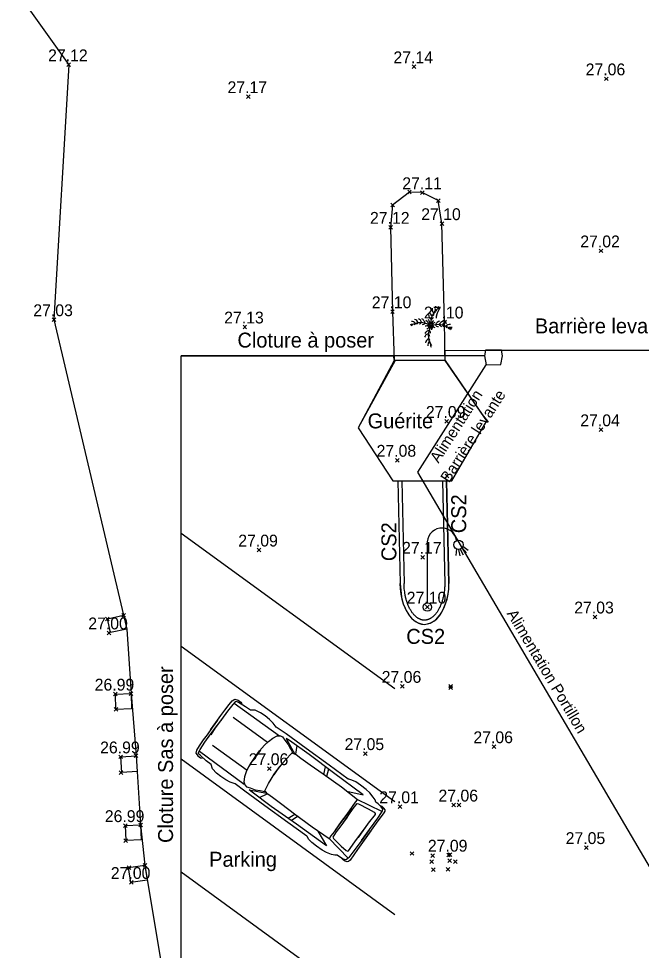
# Model space of a CAD drawing. Extents: x 37864 to 38032, y 453991 to 454052.
# Drawn here: x 37879.07 to 37894.08, y 454016.08 to 454038.52 of the extents above; entities that cross this region are included whole.
import ezdxf

# ---------------------------------------------------------------- set-up
doc = ezdxf.new("R2010")
doc.units = 0
for name, color, linetype in [('DH_CALCUL SURFACE-TEXTE', 7, 'Continuous'), ('GO_POTEAU', 7, 'Continuous'), ('PS_Bolt', 7, 'Continuous'), ('PS_Const', 7, 'Continuous'), ('PS_Dim', 7, 'Continuous'), ('PS_Hidden', 7, 'Continuous'), ('PS_Object', 7, 'Continuous'), ('PS_Plate', 7, 'Continuous'), ('PS_RoofWall', 7, 'Continuous'), ('PS_Shape', 7, 'Continuous'), ('PS_Solid', 7, 'Continuous'), ('PS_Weld', 7, 'Continuous'), ('SO_SANITAIRE DETAILLE', 7, 'Continuous')]:
    doc.layers.add(name, color=color, linetype=linetype)

# ---------------------------------------------------------------- blocks, each defined once
blk = doc.blocks.new('V-EP-CANDELAB')
for p, q in [((0, 0.1), (0, 1.5)), ((0.700628, 1.399688), (0.684459, 1.240974)), ((0.752708, 1.388229), (0.78082, 1.234594)), ((0.792944, 1.396773), (0.86024, 1.256612)), ((0.830421, 1.422331), (0.931041, 1.303495)), ((0.855244, 1.462269), (0.984837, 1.372556))]:
    blk.add_line(p, q)
for centre, radius in [((0.75, 1.5), 0.111803), ((0, 0), 0.1)]:
    blk.add_circle(centre, radius)
blk.add_arc((0.35, 1.55), 0.353553, 8.130102, 188.130102)
blk = doc.blocks.new('COCO')
blk.add_line((0.057, -0.022), (0.067, -0.026))
for points in [[(-0.124, 0.143), (-0.094, 0.115), (-0.067, 0.064), (-0.056, 0.038)], [(-0.056, 0.129), (-0.041, 0.09), (-0.035, 0.067)], [(-0.001, 0.067), (0.025, 0.08), (0.054, 0.117)], [(0.089, 0.085), (0.062, 0.069), (0.044, 0.054)], [(-0.088, -0.065), (-0.061, -0.045), (-0.025, -0.027)], [(0.018, -0.083), (0.009, -0.054), (-0.007, -0.023)]]:
    blk.add_lwpolyline(points)
for centre, radius, start, end in [((0.217, 0.419), 0.124, 153.486, 204.7238), ((0.228, 0.411), 0.0708, 123.5073, 175.8595), ((0.108, 0.288), 0.171, 185.1978, 230.7826), ((0.107, 0.35), 0.137, 181.3654, 233.0958), ((0.422, 0.078), 0.429, 127.5514, 182.6102), ((0.135, 0.395), 0.11, 162.3561, 228.705), ((0.008, 0.312), 0.0735, 282.9298, 332.2559), ((0.064, 0.356), 0.0442, 267.7529, 335.4438), ((0.113, 0.399), 0.033, 254.2928, 325.2228), ((0.16, 0.458), 0.0398, 270.4795, 326.1231), ((-0.469, -0.031), 0.0708, 68.8618, 121.214), ((-0.482, 0.051), 0.0398, 278.5982, 334.2418), ((-0.471, -0.017), 0.124, 39.9975, 91.2353), ((-0.251, -0.348), 0.429, 62.3639, 117.1699), ((-0.409, 0.068), 0.033, 279.4985, 350.4285), ((-0.415, 0.047), 0.11, 16.0163, 82.3652), ((-0.35, 0.094), 0.0442, 269.2775, 336.9684), ((-0.363, 0.053), 0.137, 11.6255, 63.3559), ((-0.286, 0.126), 0.0735, 272.4654, 321.7915), ((-0.307, 0.025), 0.171, 13.9387, 59.5235), ((-0.198, 0.112), 0.0737, 255.9805, 321.5114), ((-0.137, 0.118), 0.117, 265.9712, 314.0621), ((-0.069, 0.004), 0.00838, 155.1287, 247.6813), ((-0.035, -0.01), 0.0451, 111.1263, 157.9145), ((-0.067, 0.038), 0.0424, 263.0421, 312.9115), ((0.108, 0.203), 0.18, 192.4617, 204.4421), ((-0.006, -0.039), 0.0564, 111.1263, 157.9145), ((-0.23, -0.011), 0.18, 14.3805, 16.2304), ((-0.044, 0.06), 0.0105, 68.2237, 160.7763), ((-0.001, 0.06), 0.053, 176.1371, 214.6761), ((-0.054, 0.015), 0.0178, 333.913, 79.7857), ((-0.059, 0.017), 0.0564, 33.1475, 71.0095), ((-0.251, -0.348), 0.429, 54.2202, 60.5021), ((-0.029, 0.043), 0.0223, 247.0081, 352.8808), ((-0.03, -0.008), 0.0223, 333.913, 79.7857), ((-0.224, -0.046), 0.214, 15.7859, 18.5602), ((0.137, 0.183), 0.214, 225.9092, 228.9354), ((-0.059, 0.017), 0.0564, 24.2214, 26.0625), ((-0.048, 0.174), 0.117, 290.6592, 293.8486), ((0.015, -0.022), 0.0223, 56.5554, 162.4281), ((0.422, 0.078), 0.429, 185.1526, 190.5011), ((-0.066, 0.138), 0.132, 298.2511, 300.0757), ((0.045, 0.01), 0.053, 147.9454, 150.6531), ((0.02, 0.033), 0.0223, 171.6547, 277.5273), ((-0.017, 0.228), 0.0737, 283.2099, 348.7407), ((0.17, -0.394), 0.429, 50.4397, 113.3894), ((0.045, 0.01), 0.053, 100.7837, 124.5304), ((0.036, -0.006), 0.0178, 87.891, 158.5901), ((0.209, -0.093), 0.214, 151.1123, 151.8237), ((-0.012, 0.054), 0.0564, 308.868, 355.6561), ((0.034, 0.051), 0.0105, 352.8703, 85.4229), ((0.02, -0.028), 0.0424, 17.0201, 66.8895), ((-0.048, 0.174), 0.117, 331.1939, 338.75), ((0.209, -0.093), 0.214, 122.7468, 123.9873), ((0.279, -0.058), 0.192, 112.2412, 152.661), ((0.164, 0.046), 0.058, 195.1268, 282.5722), ((0.322, -0.023), 0.14, 101.8722, 155.687), ((0.302, 0.119), 0.137, 217.8706, 249.7656), ((0.378, -0.017), 0.109, 94.1148, 159.0322), ((0.337, 0.044), 0.0641, 200.3063, 250.058), ((0.447, -0.087), 0.123, 79.7314, 138.9221), ((-0.028, -0.321), 0.14, 105.2055, 159.0203), ((0.013, -0.284), 0.192, 108.2316, 148.6514), ((0.059, -0.221), 0.214, 133.3675, 138.1457), ((0.362, -0.23), 0.429, 147.5032, 210.4529), ((-0.165, -0.279), 0.137, 11.127, 43.022), ((-0.049, -0.022), 0.0105, 155.1287, 247.6813), ((-0.046, 0.021), 0.053, 263.0421, 312.9115), ((-0.071, -0.155), 0.058, 338.3203, 65.7657), ((-0.113, -0.103), 0.132, 37.1668, 39.7532), ((0.048, -0.002), 0.0564, 193.7688, 240.5569), ((-0.113, -0.103), 0.132, 3.3838, 8.5978), ((0.026, -0.042), 0.0105, 237.7711, 330.3237), ((-0.016, -0.034), 0.053, 345.6845, 35.5539), ((0.051, 0.021), 0.0451, 249.948, 271.8925), ((0.052, -0.015), 0.00838, 269.1067, 1.6593), ((0.119, 0.095), 0.132, 246.6411, 257.5088), ((0.391, -0.003), 0.0365, 184.8659, 248.5993), ((0.438, -0.048), 0.0241, 163.1519, 234.069), ((0.472, -0.243), 0.21, 80.7993, 105.8694), ((0.452, -0.131), 0.0708, 46.3956, 98.7477), ((0.482, -0.054), 0.0398, 193.3678, 249.0114), ((-0.023, -0.417), 0.11, 109.2993, 175.6482), ((0.044, -0.469), 0.124, 133.2805, 184.5183), ((-0.074, -0.354), 0.0442, 2.5605, 70.2514), ((-0.044, -0.412), 0.033, 12.7815, 83.7115), ((0.058, -0.467), 0.0708, 162.1448, 214.497), ((-0.023, -0.485), 0.0398, 11.8811, 67.5248)]:
    blk.add_arc(centre, radius, start, end)
blk = doc.blocks.new('POTO_REC')
at = {"layer": 'PS_Weld'}
for p, q in [((0, 1), (1, 1)), ((0, 0), (0, 1)), ((1, 1), (1, 0)), ((1, 0), (0, 0))]:
    blk.add_line(p, q, dxfattribs=at)
blk = doc.blocks.new('POINT_DISPLAY')
for p, q in [((-0.04375, -0.04375), (0.04375, 0.04375)), ((-0.04375, 0.04375), (0.04375, -0.04375))]:
    blk.add_line(p, q)
blk = doc.blocks.new('POINTCOT')
blk.add_blockref('POINT_DISPLAY', (0, 0))
blk = doc.blocks.new('2AUTOT')
at = {"layer": 'PS_Object'}
for points in [[(-2.2368, -0.1259), (-2.2386, 0.2015), (-2.2354, 0.5377), (-2.2324, 0.697), (-2.2268, 0.7426), (-2.2084, 0.7838), (-2.144, 0.8083), (-2.0432, 0.8164), (-1.9712, 0.8202), (-1.9275, 0.8508), (-1.8518, 0.8827), (-1.7249, 0.9185), (-1.608, 0.9323), (-1.4401, 0.9339), (-1.298, 0.9313), (-1.1945, 0.9113), (-1.1215, 0.8812), (-1.1104, 0.8767), (-0.5447, 0.878), (0.1409, 0.8813), (0.7386, 0.8794), (1.0309, 0.8727), (1.1466, 0.9086), (1.2652, 0.9239), (1.4092, 0.9345), (1.5433, 0.9275), (1.677, 0.9028), (1.7685, 0.8402), (1.9202, 0.833), (2.1132, 0.8123), (2.1691, 0.8089), (2.1877, 0.7793), (2.1974, 0.6996), (2.2046, 0.4901), (2.2064, 0.2453), (2.2048, -0.0084), (2.1947, -0.2029)], [(-2.2848, -0.1314), (-2.2888, 0.4217), (-2.2909, 0.7314), (-2.2836, 0.7814), (-2.2655, 0.8064), (-2.2141, 0.8192), (-2.1613, 0.8262), (-2.1183, 0.817), (-2.0976, 0.8109)], [(-2.2271, 0.7235), (-1.5742, 0.6061)], [(-1.2494, 0.6227), (-1.6267, 0.7865), (-0.7381, 0.7926), (0.002, 0.8043), (0.5788, 0.7967), (0.6713, 0.7886), (0.2844, 0.6088)], [(-0.65, 0.6296), (-0.5861, 0.8002)], [(-0.5719, 0.6231), (-0.4967, 0.7965)], [(0.2639, 0.6208), (0.3616, 0.8058)], [(1.007, -0.1403), (1.0182, 0.0307), (1.0193, 0.1767), (1.0035, 0.3523), (0.9788, 0.4823), (0.9395, 0.605), (0.8856, 0.7131), (0.8242, 0.7593), (0.7669, 0.7701), (0.68, 0.7398), (0.5514, 0.701), (0.445, 0.6503), (0.3774, 0.6228), (0.3483, 0.6068), (0.3601, 0.5536), (0.3827, 0.3957), (0.3915, 0.2688), (0.4032, 0.1301), (0.4012, 0.0239), (0.4006, -0.0941)], [(2.1886, 0.7409), (0.8432, 0.7503)], [(2.2747, -0.1136), (2.2724, 0.1046), (2.27, 0.3126), (2.2713, 0.4704), (2.2666, 0.6444), (2.2593, 0.761), (2.2286, 0.8291), (2.1508, 0.8577), (2.0757, 0.8569), (2.0322, 0.8366)], [(-1.6299, -0.0629), (-1.6283, 0.1907), (-1.6233, 0.3735), (-1.6284, 0.5254), (-1.6632, 0.5449), (-1.9214, 0.5809), (-2.084, 0.5999), (-2.1242, 0.5899), (-2.1341, 0.5723), (-2.1215, 0.3067), (-2.1311, -0.1149)], [(-1.5848, -0.2978), (-1.5832, -0.0427), (-1.5806, 0.1815), (-1.5811, 0.4086), (-1.5755, 0.5339), (-1.5821, 0.6091), (-1.0895, 0.6288), (-0.5543, 0.6215), (-0.1709, 0.614), (0.1055, 0.6117), (0.2493, 0.6106), (0.3289, 0.5937), (0.3607, 0.5846)], [(-2.2368, 0.1834), (-2.2386, -0.144), (-2.2354, -0.4802), (-2.2324, -0.6394), (-2.2268, -0.6851), (-2.2084, -0.7263), (-2.144, -0.7508), (-2.0432, -0.7588), (-1.9712, -0.7627), (-1.9275, -0.7933), (-1.8518, -0.8251), (-1.7249, -0.861), (-1.608, -0.8748), (-1.4401, -0.8764), (-1.298, -0.8738), (-1.1945, -0.8538), (-1.1215, -0.8237), (-1.1104, -0.8192), (-0.5447, -0.8205), (0.1409, -0.8238), (0.7386, -0.8219), (1.0309, -0.8151), (1.1466, -0.8511), (1.2652, -0.8663), (1.4092, -0.877), (1.5433, -0.87), (1.677, -0.8453), (1.7685, -0.7827), (1.9202, -0.7755), (2.1132, -0.7548), (2.1691, -0.7514), (2.1877, -0.7218), (2.1974, -0.642), (2.2046, -0.4326), (2.2064, -0.1878), (2.2048, 0.0659), (2.1947, 0.2605)], [(-1.5848, 0.3553), (-1.5832, 0.1002), (-1.5806, -0.1239), (-1.5811, -0.351), (-1.5755, -0.4764), (-1.5821, -0.5516), (-1.0895, -0.5712), (-0.5543, -0.564), (-0.1709, -0.5565), (0.1055, -0.5542), (0.2493, -0.5531), (0.3289, -0.5362), (0.3607, -0.5271)], [(0.9812, 0.4439), (2.0072, 0.4474)], [(-2.2848, 0.1889), (-2.2888, -0.3641), (-2.2909, -0.6738), (-2.2836, -0.7239), (-2.2655, -0.7488), (-2.2141, -0.7617), (-2.1613, -0.7686), (-2.1183, -0.7595), (-2.0976, -0.7534)], [(-1.6299, 0.1205), (-1.6283, -0.1332), (-1.6233, -0.316), (-1.6284, -0.4679), (-1.6632, -0.4874), (-1.9214, -0.5234), (-2.084, -0.5424), (-2.1242, -0.5324), (-2.1341, -0.5148), (-2.1215, -0.2492), (-2.1311, 0.1725)], [(1.007, 0.1978), (1.0182, 0.0268), (1.0193, -0.1192), (1.0035, -0.2948), (0.9788, -0.4248), (0.9395, -0.5475), (0.8856, -0.6556), (0.8242, -0.7018), (0.7669, -0.7126), (0.68, -0.6823), (0.5514, -0.6435), (0.445, -0.5928), (0.3774, -0.5653), (0.3483, -0.5493), (0.3601, -0.4961), (0.3827, -0.3382), (0.3915, -0.2113), (0.4032, -0.0725), (0.4012, 0.0336), (0.4006, 0.1516)], [(2.2747, 0.1711), (2.2724, -0.0471), (2.27, -0.2551), (2.2713, -0.4129), (2.2666, -0.5869), (2.2593, -0.7035), (2.2286, -0.7716), (2.1508, -0.8002), (2.0757, -0.7993), (2.0322, -0.779)], [(0.9812, -0.3864), (2.0072, -0.3899)], [(-2.2271, -0.666), (-1.5742, -0.5486)], [(-1.2494, -0.5652), (-1.6267, -0.7289), (-0.7381, -0.735), (0.002, -0.7468), (0.5788, -0.7392), (0.6713, -0.731), (0.2844, -0.5513)], [(-0.65, -0.5721), (-0.5861, -0.7427)], [(-0.5719, -0.5656), (-0.4967, -0.739)], [(0.2639, -0.5633), (0.3616, -0.7483)], [(2.1886, -0.6834), (0.8432, -0.6928)]]:
    blk.add_lwpolyline(points, dxfattribs=at)
blk = doc.blocks.new('AUTD')
at = {"layer": 'PS_Object'}
blk.add_blockref('2AUTOT', (-2.1886, 0.6834), dxfattribs=at)

msp = doc.modelspace()

# ---------------------------------------------------------------- linework, layer by layer
at = {"layer": 'PS_Dim'}
for p, q in [((37882.985, 454004.477), (37882.985, 454030.398)), ((37890.298, 454030.398), (37882.985, 454030.398)), ((37890.702, 454030.534), (37896.649, 454030.534))]:
    msp.add_line(p, q, dxfattribs=at)
at = {"layer": 'PS_Hidden'}
for p, q in [((37888.135, 454022.381), (37882.985, 454026.123)), ((37888.135, 454019.662), (37882.985, 454023.403)), ((37888.135, 454016.942), (37882.985, 454020.684)), ((37888.135, 454014.223), (37882.985, 454017.965))]:
    msp.add_line(p, q, dxfattribs=at)
at = {"layer": 'PS_Object'}
for p, q in [((37888.689, 454027.599), (37890.334, 454030.185)), ((37895.353, 454016.257), (37888.689, 454027.599))]:
    msp.add_line(p, q, dxfattribs=at)
msp.add_lwpolyline([(37882.985, 454004.477), (37882.985, 454030.398), (37888.093, 454030.398), (37888.117, 454030.285), (37887.249, 454028.666), (37888.087, 454027.388), (37888.205, 454027.388), (37888.26, 454024.917), (37888.293, 454024.591), (37888.339, 454024.424), (37888.407, 454024.265), (37888.488, 454024.141), (37888.536, 454024.084), (37888.591, 454024.033), (37888.65, 454023.991), (37888.708, 454023.962), (37888.779, 454023.94), (37888.849, 454023.934), (37888.985, 454023.959), (37889.121, 454024.044), (37889.24, 454024.186), (37889.319, 454024.328), (37889.374, 454024.475), (37889.41, 454024.622), (37889.433, 454024.777), (37889.438, 454024.917), (37889.382, 454027.388), (37889.512, 454027.388), (37890.353, 454028.831), (37889.352, 454030.285), (37889.343, 454030.528), (37899.117, 454030.549)], dxfattribs=at)
at = {"layer": 'PS_Plate'}
msp.add_lwpolyline([(37890.323, 454030.534), (37890.298, 454030.398), (37890.334, 454030.185), (37890.688, 454030.19), (37890.729, 454030.398), (37890.702, 454030.534), (37890.323, 454030.534)], dxfattribs=at)
at = {"layer": 'PS_Shape'}
msp.add_line((37889.382, 454027.388), (37889.438, 454024.917), dxfattribs=at)
at = {"layer": 'PS_Solid'}
msp.add_lwpolyline([(37888.144, 454030.285), (37887.249, 454028.666), (37888.087, 454027.388), (37889.512, 454027.388), (37890.353, 454028.831), (37889.354, 454030.285), (37888.144, 454030.285)], dxfattribs=at)
at = {"layer": 'SO_SANITAIRE DETAILLE'}
for p, q in [((37882.985, 454004.477), (37882.985, 454030.285)), ((37888.205, 454027.388), (37888.261, 454024.917)), ((37888.305, 454027.39), (37888.361, 454024.919)), ((37889.282, 454027.385), (37889.338, 454024.914)), ((37889.382, 454027.388), (37889.438, 454024.917))]:
    msp.add_line(p, q, dxfattribs=at)
for points in [[(37877.767, 454040.919), (37880.278, 454037.408), (37879.922, 454031.271), (37881.601, 454024.153), (37881.601, 454024.153), (37881.601, 454024.153), (37881.675, 454023.821), (37881.781, 454022.267), (37881.901, 454020.769), (37881.927, 454020.39), (37882.008, 454019.105), (37882.114, 454018.134), (37882.561, 454015.43), (37882.656, 454013.593), (37882.577, 454012.12), (37882.592, 454010.925), (37882.785, 454009.367), (37882.96, 454007.587), (37882.985, 454004.477)], [(37889.352, 454030.285), (37889.334, 454031.215), (37889.269, 454033.583), (37889.181, 454034.136), (37888.798, 454034.328), (37888.489, 454034.343), (37888.081, 454034.029), (37888.035, 454033.494), (37888.079, 454031.462), (37888.117, 454030.285)]]:
    msp.add_lwpolyline(points, dxfattribs=at)
msp.add_ellipse((37888.849, 454024.917), major_axis=(0, 0.983), ratio=0.599267, start_param=1.570796, end_param=4.712389, dxfattribs=at)
msp.add_open_spline([(37889.338, 454024.917), (37889.338, 454024.855), (37889.334, 454024.795), (37889.323, 454024.706), (37889.319, 454024.677), (37889.309, 454024.62), (37889.303, 454024.592), (37889.289, 454024.537), (37889.281, 454024.51), (37889.265, 454024.458), (37889.256, 454024.433), (37889.236, 454024.384), (37889.226, 454024.36), (37889.203, 454024.315), (37889.192, 454024.294), (37889.167, 454024.252), (37889.154, 454024.233), (37889.128, 454024.197), (37889.115, 454024.181), (37889.087, 454024.151), (37889.074, 454024.137), (37889.046, 454024.112), (37889.031, 454024.101), (37889.003, 454024.081), (37888.989, 454024.073), (37888.968, 454024.062), (37888.961, 454024.059), (37888.947, 454024.053), (37888.94, 454024.05), (37888.926, 454024.045), (37888.919, 454024.043), (37888.905, 454024.04), (37888.898, 454024.038), (37888.884, 454024.036), (37888.877, 454024.035), (37888.863, 454024.034), (37888.856, 454024.034), (37888.842, 454024.034), (37888.835, 454024.034), (37888.821, 454024.035), (37888.814, 454024.036), (37888.8, 454024.038), (37888.793, 454024.04), (37888.779, 454024.043), (37888.772, 454024.045), (37888.758, 454024.05), (37888.751, 454024.053), (37888.737, 454024.059), (37888.73, 454024.062), (37888.709, 454024.073), (37888.694, 454024.081), (37888.666, 454024.101), (37888.652, 454024.112), (37888.624, 454024.137), (37888.61, 454024.151), (37888.583, 454024.181), (37888.569, 454024.197), (37888.543, 454024.233), (37888.53, 454024.252), (37888.506, 454024.294), (37888.494, 454024.315), (37888.472, 454024.36), (37888.461, 454024.384), (37888.442, 454024.433), (37888.433, 454024.458), (37888.416, 454024.51), (37888.408, 454024.537), (37888.395, 454024.592), (37888.389, 454024.62), (37888.378, 454024.677), (37888.374, 454024.706), (37888.363, 454024.795), (37888.36, 454024.855), (37888.36, 454024.917)], degree=3, dxfattribs=at)

# ---------------------------------------------------------------- block references
at = {"layer": 'DH_CALCUL SURFACE-TEXTE', "rotation": 2.2526485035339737e-05}
for p in [(37880.278, 454037.408), (37888.599, 454037.359), (37893.232, 454037.069), (37884.602, 454036.64), (37888.489, 454034.343), (37888.798, 454034.328), (37889.181, 454034.136), (37888.081, 454034.029), (37888.035, 454033.494), (37889.269, 454033.583), (37893.102, 454032.927), (37888.079, 454031.462), (37879.922, 454031.271), (37889.334, 454031.215), (37884.521, 454031.094), (37889.008, 454031.118), (37889.381, 454028.822), (37893.102, 454028.62), (37888.194, 454027.886), (37889.394, 454027.509), (37884.861, 454025.724), (37888.808, 454025.55), (37888.92, 454024.35), (37881.208, 454024.066), (37881.601, 454024.153), (37892.956, 454024.112), (37881.246, 454023.729), (37888.317, 454022.442), (37889.481, 454022.445), (37881.401, 454022.255), (37881.781, 454022.267), (37889.48, 454022.41), (37881.415, 454021.889), (37890.526, 454020.988), (37881.532, 454020.744), (37881.901, 454020.769), (37887.422, 454020.823), (37885.113, 454020.46), (37881.54, 454020.365), (37888.26, 454019.545), (37889.553, 454019.581), (37889.685, 454019.585), (37881.645, 454019.089), (37882.008, 454019.105), (37881.646, 454018.724), (37888.55, 454018.416), (37889.465, 454018.387), (37892.75, 454018.56), (37889.026, 454018.217), (37889.05, 454018.363), (37889.429, 454018.377), (37889.456, 454018.241), (37889.591, 454018.219), (37881.729, 454018.077), (37882.114, 454018.134), (37889.061, 454018.028), (37889.415, 454018.032), (37881.789, 454017.721)]:
    msp.add_blockref('POINTCOT', p, dxfattribs=at)
at = {"layer": 'PS_Bolt'}
for p, xscale, yscale, rotation in [((37881.601, 454024.153), 0.4, 0.3400000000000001, -167.44146717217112), ((37881.781, 454022.267), 0.3800000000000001, 0.37, -178.2062050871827), ((37881.901, 454020.769), 0.37000000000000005, 0.38, -176.09201026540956), ((37882.008, 454019.105), 0.3599999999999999, 0.35999999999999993, -177.5289290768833), ((37882.114, 454018.134), 0.4000000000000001, 0.3599999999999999, -171.57385078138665)]:
    msp.add_blockref('POTO_REC', p, dxfattribs=dict(at, xscale=xscale, yscale=yscale, rotation=rotation))
at = {"layer": 'PS_Const', "rotation": 2.2526485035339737e-05}
msp.add_blockref('COCO', (37889.008, 454031.118), dxfattribs=at)
at = {"layer": 'PS_Hidden', "rotation": 143.99999999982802}
msp.add_blockref('AUTD', (37884.263, 454022.035), dxfattribs=at)
at = {"layer": 'PS_RoofWall', "rotation": 2.2526485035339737e-05}
msp.add_blockref('V-EP-CANDELAB', (37888.92, 454024.35), dxfattribs=at)

# ---------------------------------------------------------------- texts
at = {"layer": 'GO_POTEAU'}
for s, p in [('27.12', (37879.78, 454037.492)), ('27.14', (37888.101, 454037.443)), ('27.06', (37892.734, 454037.153)), ('27.17', (37884.104, 454036.724)), ('27.11', (37888.315, 454034.412)), ('27.10', (37888.771, 454033.667)), ('27.12', (37887.537, 454033.578)), ('27.02', (37892.604, 454033.011)), ('27.10', (37887.581, 454031.546)), ('27.03', (37879.424, 454031.354)), ('27.13', (37884.023, 454031.178)), ('27.10', (37888.836, 454031.299)), ('27.09', (37888.883, 454028.906)), ('27.04', (37892.604, 454028.704)), ('27.08', (37887.696, 454027.97)), ('27.09', (37884.363, 454025.808)), ('27.17', (37888.31, 454025.634)), ('27.10', (37888.422, 454024.433)), ('27.03', (37892.458, 454024.196)), ('27.00', (37880.748, 454023.813)), ('27.06', (37887.819, 454022.526)), ('26.99', (37880.903, 454022.339)), ('27.06', (37890.028, 454021.072)), ('27.05', (37886.924, 454020.907)), ('26.99', (37881.034, 454020.827)), ('27.06', (37884.615, 454020.544)), ('27.01', (37887.762, 454019.628)), ('27.06', (37889.187, 454019.668)), ('26.99', (37881.147, 454019.173)), ('27.05', (37892.252, 454018.644)), ('27.09', (37888.931, 454018.461)), ('27.00', (37881.292, 454017.804))]:
    msp.add_text(s, height=0.285, rotation=0, dxfattribs=at).set_placement(p)
at = {"layer": 'PS_Hidden'}
for s, rotation, p in [('Barrière levante', 360, (37891.51, 454030.94)), ('Cloture à poser', 360, (37884.343, 454030.598)), ('Guérite', 360, (37887.479, 454028.653)), ('CS2', 90, (37889.855, 454026.128)), ('CS2', 90, (37888.172, 454025.455)), ('CS2', 360, (37888.411, 454023.464)), ('Cloture Sas à poser', 90, (37882.791, 454018.67)), ('Parking', 360, (37883.662, 454018.097))]:
    msp.add_text(s, height=0.36, rotation=rotation, dxfattribs=at).set_placement(p)
at = {"layer": 'PS_Object'}
for s, rotation, p in [('Alimentation', 57.2637, (37889.188, 454027.799)), ('Barrière levante', 57.2637, (37889.442, 454027.325)), ('Alimentation Portillon', 300.6812, (37890.823, 454024.195))]:
    msp.add_text(s, height=0.27, rotation=rotation, dxfattribs=at).set_placement(p)

doc.saveas('drawing.dxf')
